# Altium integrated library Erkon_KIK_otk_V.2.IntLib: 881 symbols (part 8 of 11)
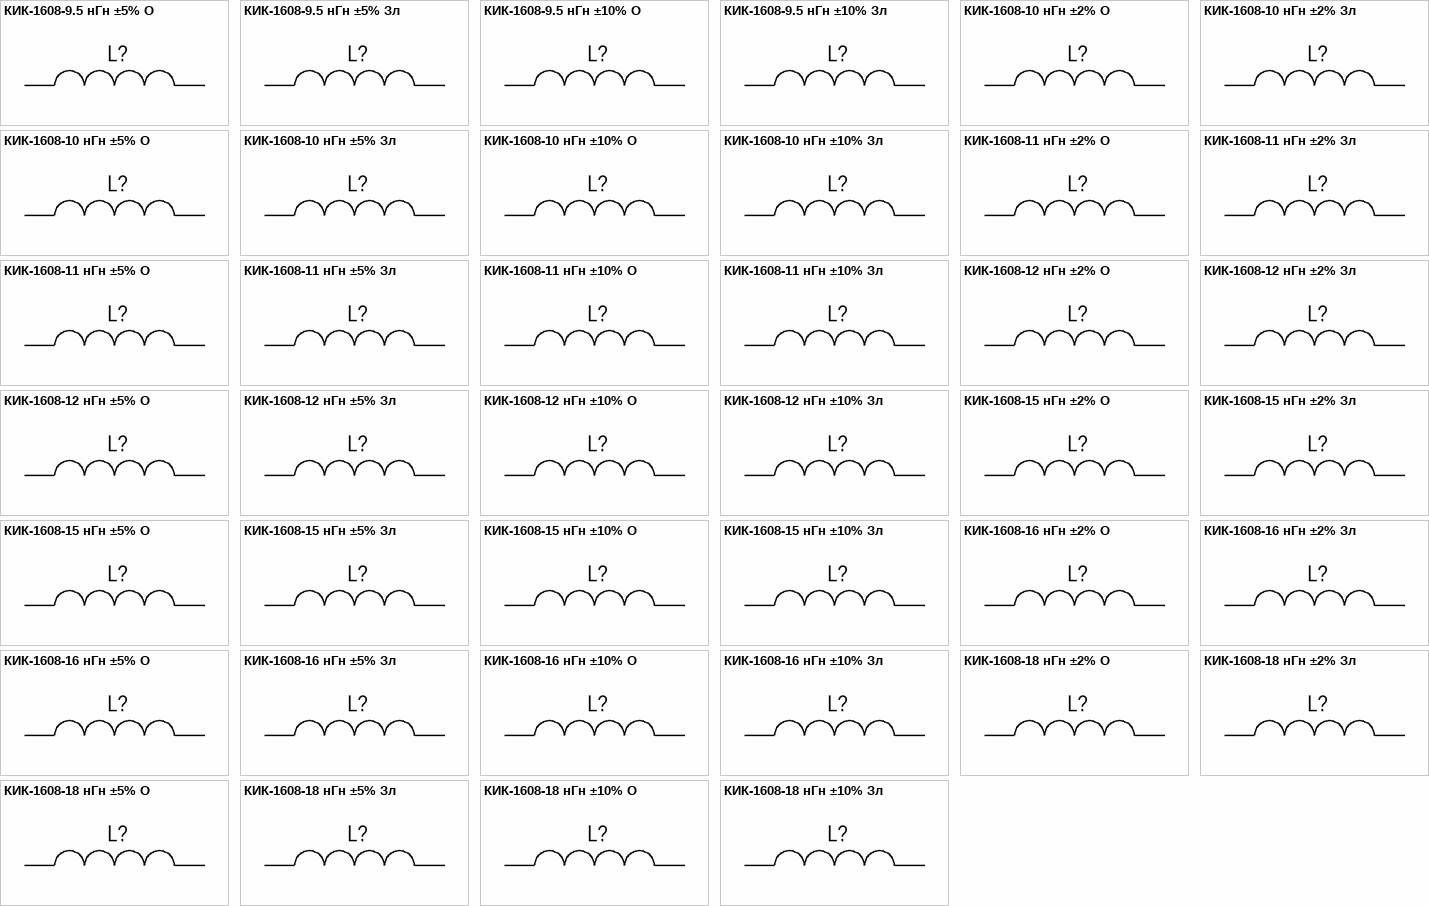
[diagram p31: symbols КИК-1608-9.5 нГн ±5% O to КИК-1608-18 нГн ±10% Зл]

## КИК-1608-15 нГн ±2% Зл
designator L?, comment 15 нГн ±2%  (value not drawn)
Катушка индуктивности с керамическим сердечником и золотым покрытием контактных площадок; Номиналиная индуктивность: 15 нГн; Добротность, не менее: 30; Резонансная частота, не менее: 4.00 ГГц; Сопротивление обмотки постоянноми току, не более: 0.170 Ом; Допустимый ток обмотки: 700 мА; Диапазон рабочих температур: от -60 до +125 ℃; Упаковка: Катушка и лента; Типоразмер: 1608 (0603); Технология монтажа: SMT; Изготовитель: АО "НПО "ЭРКОН"
footprint КИК-1608_Зл (Катушка индуктивности с керамическим сердечником  типоразмер 1005(0402))
pins: 1, 2

## КИК-1608-15 нГн ±5% O
designator L?, comment 15 нГн ±5%  (value not drawn)
Катушка индуктивности с керамическим сердечником и  финишным покрытием контактных площадок оловом; Номиналиная индуктивность: 12 нГн; Добротность, не менее: 30; Резонансная частота, не менее: 4.00 ГГц; Сопротивление обмотки постоянноми току, не более: 0.170 Ом; Допустимый ток обмотки: 700 мА; Диапазон рабочих температур: от -60 до +125 ℃; Упаковка: Катушка и лента; Типоразмер: 1608 (0603); Технология монтажа: SMT; Изготовитель: АО "НПО "ЭРКОН"
footprint КИК-1608_О (Катушка индуктивности с керамическим сердечником  типоразмер 1005(0402))
pins: 1, 2

## КИК-1608-15 нГн ±5% Зл
designator L?, comment 15 нГн ±5%  (value not drawn)
Катушка индуктивности с керамическим сердечником и золотым покрытием контактных площадок; Номиналиная индуктивность: 15 нГн; Добротность, не менее: 30; Резонансная частота, не менее: 4.00 ГГц; Сопротивление обмотки постоянноми току, не более: 0.170 Ом; Допустимый ток обмотки: 700 мА; Диапазон рабочих температур: от -60 до +125 ℃; Упаковка: Катушка и лента; Типоразмер: 1608 (0603); Технология монтажа: SMT; Изготовитель: АО "НПО "ЭРКОН"
footprint КИК-1608_Зл (Катушка индуктивности с керамическим сердечником  типоразмер 1005(0402))
pins: 1, 2

## КИК-1608-15 нГн ±10% O
designator L?, comment 15 нГн ±10%  (value not drawn)
Катушка индуктивности с керамическим сердечником и  финишным покрытием контактных площадок оловом; Номиналиная индуктивность: 15 нГн; Добротность, не менее: 30; Резонансная частота, не менее: 4.00 ГГц; Сопротивление обмотки постоянноми току, не более: 0.170 Ом; Допустимый ток обмотки: 700 мА; Диапазон рабочих температур: от -60 до +125 ℃; Упаковка: Катушка и лента; Типоразмер: 1608 (0603); Технология монтажа: SMT; Изготовитель: АО "НПО "ЭРКОН"
footprint КИК-1608_О (Катушка индуктивности с керамическим сердечником  типоразмер 1005(0402))
pins: 1, 2

## КИК-1608-15 нГн ±10% Зл
designator L?, comment 15 нГн ±10%  (value not drawn)
Катушка индуктивности с керамическим сердечником и золотым покрытием контактных площадок; Номиналиная индуктивность: 15 нГн; Добротность, не менее: 30; Резонансная частота, не менее: 4.00 ГГц; Сопротивление обмотки постоянноми току, не более: 0.170 Ом; Допустимый ток обмотки: 700 мА; Диапазон рабочих температур: от -60 до +125 ℃; Упаковка: Катушка и лента; Типоразмер: 1608 (0603); Технология монтажа: SMT; Изготовитель: АО "НПО "ЭРКОН"
footprint КИК-1608_Зл (Катушка индуктивности с керамическим сердечником  типоразмер 1005(0402))
pins: 1, 2

## КИК-1608-16 нГн ±2% O
designator L?, comment 16 нГн ±2%  (value not drawn)
Катушка индуктивности с керамическим сердечником и  финишным покрытием контактных площадок оловом; Номиналиная индуктивность: 16 нГн; Добротность, не менее: 30; Резонансная частота, не менее: 3.30 ГГц; Сопротивление обмотки постоянноми току, не более: 0.170 Ом; Допустимый ток обмотки: 700 мА; Диапазон рабочих температур: от -60 до +125 ℃; Упаковка: Катушка и лента; Типоразмер: 1608 (0603); Технология монтажа: SMT; Изготовитель: АО "НПО "ЭРКОН"
footprint КИК-1608_О (Катушка индуктивности с керамическим сердечником  типоразмер 1005(0402))
pins: 1, 2

## КИК-1608-16 нГн ±2% Зл
designator L?, comment 16 нГн ±2%  (value not drawn)
Катушка индуктивности с керамическим сердечником и золотым покрытием контактных площадок; Номиналиная индуктивность: 16 нГн; Добротность, не менее: 30; Резонансная частота, не менее: 3.30 ГГц; Сопротивление обмотки постоянноми току, не более: 0.170 Ом; Допустимый ток обмотки: 700 мА; Диапазон рабочих температур: от -60 до +125 ℃; Упаковка: Катушка и лента; Типоразмер: 1608 (0603); Технология монтажа: SMT; Изготовитель: АО "НПО "ЭРКОН"
footprint КИК-1608_Зл (Катушка индуктивности с керамическим сердечником  типоразмер 1005(0402))
pins: 1, 2

## КИК-1608-16 нГн ±5% O
designator L?, comment 16 нГн ±5%  (value not drawn)
Катушка индуктивности с керамическим сердечником и  финишным покрытием контактных площадок оловом; Номиналиная индуктивность: 16 нГн; Добротность, не менее: 30; Резонансная частота, не менее: 3.30 ГГц; Сопротивление обмотки постоянноми току, не более: 0.170 Ом; Допустимый ток обмотки: 700 мА; Диапазон рабочих температур: от -60 до +125 ℃; Упаковка: Катушка и лента; Типоразмер: 1608 (0603); Технология монтажа: SMT; Изготовитель: АО "НПО "ЭРКОН"
footprint КИК-1608_О (Катушка индуктивности с керамическим сердечником  типоразмер 1005(0402))
pins: 1, 2

## КИК-1608-16 нГн ±5% Зл
designator L?, comment 16 нГн ±5%  (value not drawn)
Катушка индуктивности с керамическим сердечником и золотым покрытием контактных площадок; Номиналиная индуктивность: 16 нГн; Добротность, не менее: 30; Резонансная частота, не менее: 3.30 ГГц; Сопротивление обмотки постоянноми току, не более: 0.170 Ом; Допустимый ток обмотки: 700 мА; Диапазон рабочих температур: от -60 до +125 ℃; Упаковка: Катушка и лента; Типоразмер: 1608 (0603); Технология монтажа: SMT; Изготовитель: АО "НПО "ЭРКОН"
footprint КИК-1608_Зл (Катушка индуктивности с керамическим сердечником  типоразмер 1005(0402))
pins: 1, 2

## КИК-1608-16 нГн ±10% O
designator L?, comment 16 нГн ±10%  (value not drawn)
Катушка индуктивности с керамическим сердечником и  финишным покрытием контактных площадок оловом; Номиналиная индуктивность: 16 нГн; Добротность, не менее: 30; Резонансная частота, не менее: 3.30 ГГц; Сопротивление обмотки постоянноми току, не более: 0.170 Ом; Допустимый ток обмотки: 700 мА; Диапазон рабочих температур: от -60 до +125 ℃; Упаковка: Катушка и лента; Типоразмер: 1608 (0603); Технология монтажа: SMT; Изготовитель: АО "НПО "ЭРКОН"
footprint КИК-1608_О (Катушка индуктивности с керамическим сердечником  типоразмер 1005(0402))
pins: 1, 2

## КИК-1608-16 нГн ±10% Зл
designator L?, comment 16 нГн ±10%  (value not drawn)
Катушка индуктивности с керамическим сердечником и золотым покрытием контактных площадок; Номиналиная индуктивность: 16 нГн; Добротность, не менее: 30; Резонансная частота, не менее: 3.30 ГГц; Сопротивление обмотки постоянноми току, не более: 0.170 Ом; Допустимый ток обмотки: 700 мА; Диапазон рабочих температур: от -60 до +125 ℃; Упаковка: Катушка и лента; Типоразмер: 1608 (0603); Технология монтажа: SMT; Изготовитель: АО "НПО "ЭРКОН"
footprint КИК-1608_Зл (Катушка индуктивности с керамическим сердечником  типоразмер 1005(0402))
pins: 1, 2

## КИК-1608-18 нГн ±2% O
designator L?, comment 18 нГн ±2%  (value not drawn)
Катушка индуктивности с керамическим сердечником и  финишным покрытием контактных площадок оловом; Номиналиная индуктивность: 18 нГн; Добротность, не менее: 30; Резонансная частота, не менее: 3.10 ГГц; Сопротивление обмотки постоянноми току, не более: 0.170 Ом; Допустимый ток обмотки: 700 мА; Диапазон рабочих температур: от -60 до +125 ℃; Упаковка: Катушка и лента; Типоразмер: 1608 (0603); Технология монтажа: SMT; Изготовитель: АО "НПО "ЭРКОН"
footprint КИК-1608_О (Катушка индуктивности с керамическим сердечником  типоразмер 1005(0402))
pins: 1, 2

## КИК-1608-18 нГн ±2% Зл
designator L?, comment 18 нГн ±2%  (value not drawn)
Катушка индуктивности с керамическим сердечником и золотым покрытием контактных площадок; Номиналиная индуктивность: 18 нГн; Добротность, не менее: 30; Резонансная частота, не менее: 3.10 ГГц; Сопротивление обмотки постоянноми току, не более: 0.170 Ом; Допустимый ток обмотки: 700 мА; Диапазон рабочих температур: от -60 до +125 ℃; Упаковка: Катушка и лента; Типоразмер: 1608 (0603); Технология монтажа: SMT; Изготовитель: АО "НПО "ЭРКОН"
footprint КИК-1608_Зл (Катушка индуктивности с керамическим сердечником  типоразмер 1005(0402))
pins: 1, 2

## КИК-1608-18 нГн ±5% O
designator L?, comment 18 нГн ±5%  (value not drawn)
Катушка индуктивности с керамическим сердечником и  финишным покрытием контактных площадок оловом; Номиналиная индуктивность: 18 нГн; Добротность, не менее: 30; Резонансная частота, не менее: 3.10 ГГц; Сопротивление обмотки постоянноми току, не более: 0.170 Ом; Допустимый ток обмотки: 700 мА; Диапазон рабочих температур: от -60 до +125 ℃; Упаковка: Катушка и лента; Типоразмер: 1608 (0603); Технология монтажа: SMT; Изготовитель: АО "НПО "ЭРКОН"
footprint КИК-1608_О (Катушка индуктивности с керамическим сердечником  типоразмер 1005(0402))
pins: 1, 2

## КИК-1608-18 нГн ±5% Зл
designator L?, comment 18 нГн ±5%  (value not drawn)
Катушка индуктивности с керамическим сердечником и золотым покрытием контактных площадок; Номиналиная индуктивность: 18 нГн; Добротность, не менее: 30; Резонансная частота, не менее: 3.10 ГГц; Сопротивление обмотки постоянноми току, не более: 0.170 Ом; Допустимый ток обмотки: 700 мА; Диапазон рабочих температур: от -60 до +125 ℃; Упаковка: Катушка и лента; Типоразмер: 1608 (0603); Технология монтажа: SMT; Изготовитель: АО "НПО "ЭРКОН"
footprint КИК-1608_Зл (Катушка индуктивности с керамическим сердечником  типоразмер 1005(0402))
pins: 1, 2

## КИК-1608-18 нГн ±10% O
designator L?, comment 18 нГн ±10%  (value not drawn)
Катушка индуктивности с керамическим сердечником и  финишным покрытием контактных площадок оловом; Номиналиная индуктивность: 18 нГн; Добротность, не менее: 30; Резонансная частота, не менее: 3.10 ГГц; Сопротивление обмотки постоянноми току, не более: 0.170 Ом; Допустимый ток обмотки: 700 мА; Диапазон рабочих температур: от -60 до +125 ℃; Упаковка: Катушка и лента; Типоразмер: 1608 (0603); Технология монтажа: SMT; Изготовитель: АО "НПО "ЭРКОН"
footprint КИК-1608_О (Катушка индуктивности с керамическим сердечником  типоразмер 1005(0402))
pins: 1, 2

## КИК-1608-18 нГн ±10% Зл
designator L?, comment 18 нГн ±10%  (value not drawn)
Катушка индуктивности с керамическим сердечником и золотым покрытием контактных площадок; Номиналиная индуктивность: 18 нГн; Добротность, не менее: 30; Резонансная частота, не менее: 3.10 ГГц; Сопротивление обмотки постоянноми току, не более: 0.170 Ом; Допустимый ток обмотки: 700 мА; Диапазон рабочих температур: от -60 до +125 ℃; Упаковка: Катушка и лента; Типоразмер: 1608 (0603); Технология монтажа: SMT; Изготовитель: АО "НПО "ЭРКОН"
footprint КИК-1608_Зл (Катушка индуктивности с керамическим сердечником  типоразмер 1005(0402))
pins: 1, 2

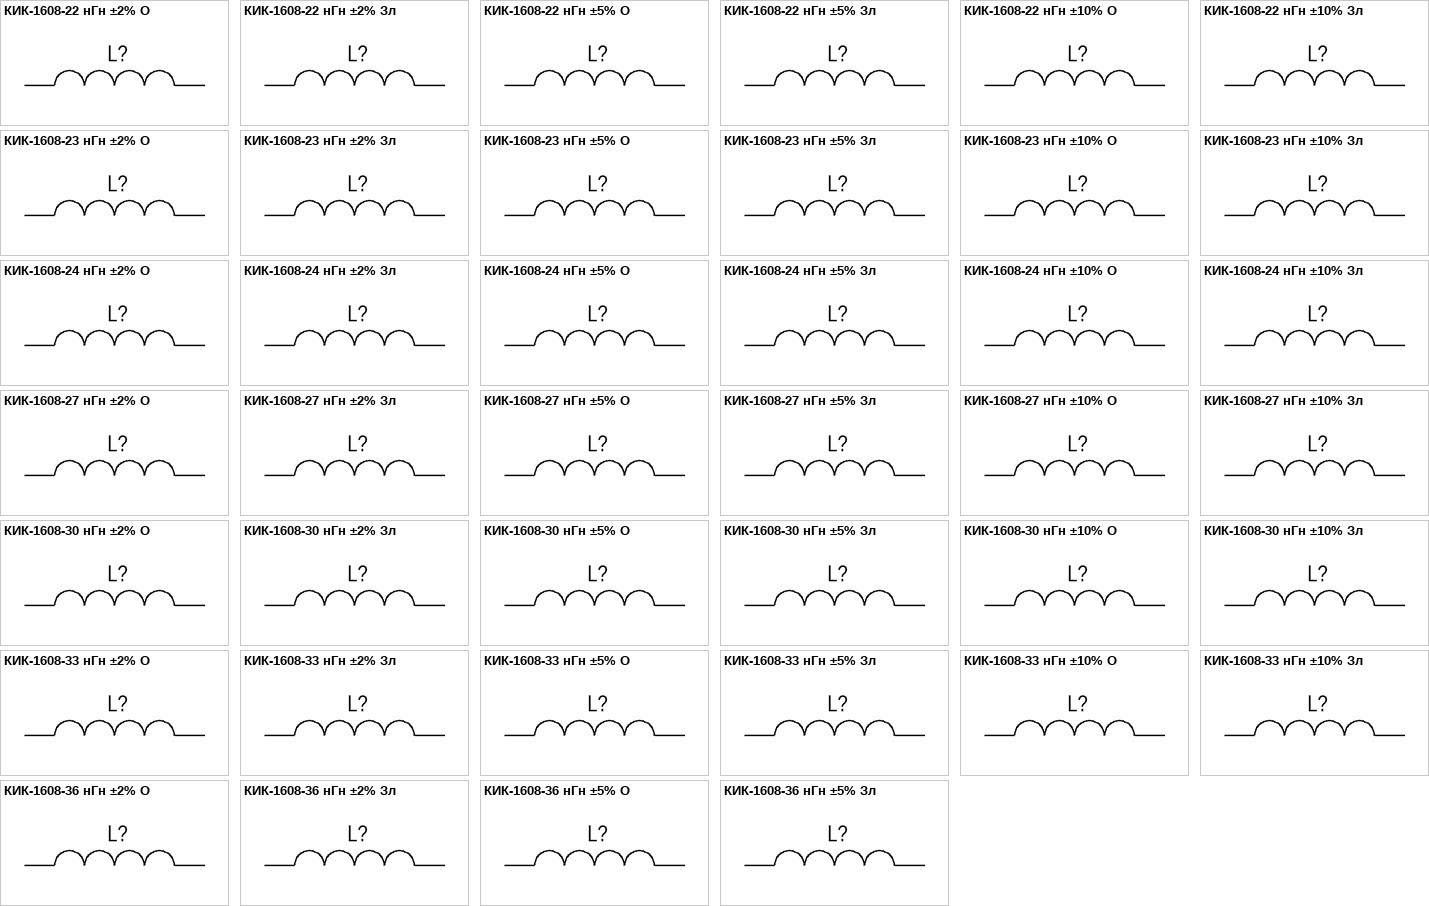
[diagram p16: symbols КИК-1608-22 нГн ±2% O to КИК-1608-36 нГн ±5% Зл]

## КИК-1608-22 нГн ±2% O
designator L?, comment 22 нГн ±2%  (value not drawn)
Катушка индуктивности с керамическим сердечником и  финишным покрытием контактных площадок оловом; Номиналиная индуктивность: 22 нГн; Добротность, не менее: 35; Резонансная частота, не менее: 3.00 ГГц; Сопротивление обмотки постоянноми току, не более: 0.190 Ом; Допустимый ток обмотки: 700 мА; Диапазон рабочих температур: от -60 до +125 ℃; Упаковка: Катушка и лента; Типоразмер: 1608 (0603); Технология монтажа: SMT; Изготовитель: АО "НПО "ЭРКОН"
footprint КИК-1608_О (Катушка индуктивности с керамическим сердечником  типоразмер 1005(0402))
pins: 1, 2

## КИК-1608-22 нГн ±2% Зл
designator L?, comment 22 нГн ±2%  (value not drawn)
Катушка индуктивности с керамическим сердечником и золотым покрытием контактных площадок; Номиналиная индуктивность: 22 нГн; Добротность, не менее: 35; Резонансная частота, не менее: 3.00 ГГц; Сопротивление обмотки постоянноми току, не более: 0.190 Ом; Допустимый ток обмотки: 700 мА; Диапазон рабочих температур: от -60 до +125 ℃; Упаковка: Катушка и лента; Типоразмер: 1608 (0603); Технология монтажа: SMT; Изготовитель: АО "НПО "ЭРКОН"
footprint КИК-1608_Зл (Катушка индуктивности с керамическим сердечником  типоразмер 1005(0402))
pins: 1, 2

## КИК-1608-22 нГн ±5% O
designator L?, comment 22 нГн ±5%  (value not drawn)
Катушка индуктивности с керамическим сердечником и  финишным покрытием контактных площадок оловом; Номиналиная индуктивность: 22 нГн; Добротность, не менее: 35; Резонансная частота, не менее: 3.00 ГГц; Сопротивление обмотки постоянноми току, не более: 0.190 Ом; Допустимый ток обмотки: 700 мА; Диапазон рабочих температур: от -60 до +125 ℃; Упаковка: Катушка и лента; Типоразмер: 1608 (0603); Технология монтажа: SMT; Изготовитель: АО "НПО "ЭРКОН"
footprint КИК-1608_О (Катушка индуктивности с керамическим сердечником  типоразмер 1005(0402))
pins: 1, 2

## КИК-1608-22 нГн ±5% Зл
designator L?, comment 22 нГн ±5%  (value not drawn)
Катушка индуктивности с керамическим сердечником и золотым покрытием контактных площадок; Номиналиная индуктивность: 22 нГн; Добротность, не менее: 35; Резонансная частота, не менее: 3.00 ГГц; Сопротивление обмотки постоянноми току, не более: 0.190 Ом; Допустимый ток обмотки: 700 мА; Диапазон рабочих температур: от -60 до +125 ℃; Упаковка: Катушка и лента; Типоразмер: 1608 (0603); Технология монтажа: SMT; Изготовитель: АО "НПО "ЭРКОН"
footprint КИК-1608_Зл (Катушка индуктивности с керамическим сердечником  типоразмер 1005(0402))
pins: 1, 2

## КИК-1608-22 нГн ±10% O
designator L?, comment 22 нГн ±10%  (value not drawn)
Катушка индуктивности с керамическим сердечником и  финишным покрытием контактных площадок оловом; Номиналиная индуктивность: 22 нГн; Добротность, не менее: 35; Резонансная частота, не менее: 3.00 ГГц; Сопротивление обмотки постоянноми току, не более: 0.190 Ом; Допустимый ток обмотки: 700 мА; Диапазон рабочих температур: от -60 до +125 ℃; Упаковка: Катушка и лента; Типоразмер: 1608 (0603); Технология монтажа: SMT; Изготовитель: АО "НПО "ЭРКОН"
footprint КИК-1608_О (Катушка индуктивности с керамическим сердечником  типоразмер 1005(0402))
pins: 1, 2

## КИК-1608-22 нГн ±10% Зл
designator L?, comment 22 нГн ±10%  (value not drawn)
Катушка индуктивности с керамическим сердечником и золотым покрытием контактных площадок; Номиналиная индуктивность: 22 нГн; Добротность, не менее: 35; Резонансная частота, не менее: 3.00 ГГц; Сопротивление обмотки постоянноми току, не более: 0.190 Ом; Допустимый ток обмотки: 700 мА; Диапазон рабочих температур: от -60 до +125 ℃; Упаковка: Катушка и лента; Типоразмер: 1608 (0603); Технология монтажа: SMT; Изготовитель: АО "НПО "ЭРКОН"
footprint КИК-1608_Зл (Катушка индуктивности с керамическим сердечником  типоразмер 1005(0402))
pins: 1, 2

## КИК-1608-23 нГн ±2% O
designator L?, comment 23 нГн ±2%  (value not drawn)
Катушка индуктивности с керамическим сердечником и  финишным покрытием контактных площадок оловом; Номиналиная индуктивность: 23 нГн; Добротность, не менее: 35; Резонансная частота, не менее: 2.85 ГГц; Сопротивление обмотки постоянноми току, не более: 0.190 Ом; Допустимый ток обмотки: 700 мА; Диапазон рабочих температур: от -60 до +125 ℃; Упаковка: Катушка и лента; Типоразмер: 1608 (0603); Технология монтажа: SMT; Изготовитель: АО "НПО "ЭРКОН"
footprint КИК-1608_О (Катушка индуктивности с керамическим сердечником  типоразмер 1005(0402))
pins: 1, 2

## КИК-1608-23 нГн ±2% Зл
designator L?, comment 23 нГн ±2%  (value not drawn)
Катушка индуктивности с керамическим сердечником и золотым покрытием контактных площадок; Номиналиная индуктивность: 23 нГн; Добротность, не менее: 35; Резонансная частота, не менее: 2.85 ГГц; Сопротивление обмотки постоянноми току, не более: 0.190 Ом; Допустимый ток обмотки: 700 мА; Диапазон рабочих температур: от -60 до +125 ℃; Упаковка: Катушка и лента; Типоразмер: 1608 (0603); Технология монтажа: SMT; Изготовитель: АО "НПО "ЭРКОН"
footprint КИК-1608_Зл (Катушка индуктивности с керамическим сердечником  типоразмер 1005(0402))
pins: 1, 2

## КИК-1608-23 нГн ±5% O
designator L?, comment 23 нГн ±5%  (value not drawn)
Катушка индуктивности с керамическим сердечником и  финишным покрытием контактных площадок оловом; Номиналиная индуктивность: 23 нГн; Добротность, не менее: 35; Резонансная частота, не менее: 2.85 ГГц; Сопротивление обмотки постоянноми току, не более: 0.190 Ом; Допустимый ток обмотки: 700 мА; Диапазон рабочих температур: от -60 до +125 ℃; Упаковка: Катушка и лента; Типоразмер: 1608 (0603); Технология монтажа: SMT; Изготовитель: АО "НПО "ЭРКОН"
footprint КИК-1608_О (Катушка индуктивности с керамическим сердечником  типоразмер 1005(0402))
pins: 1, 2

## КИК-1608-23 нГн ±5% Зл
designator L?, comment 23 нГн ±5%  (value not drawn)
Катушка индуктивности с керамическим сердечником и золотым покрытием контактных площадок; Номиналиная индуктивность: 23 нГн; Добротность, не менее: 35; Резонансная частота, не менее: 2.85 ГГц; Сопротивление обмотки постоянноми току, не более: 0.190 Ом; Допустимый ток обмотки: 700 мА; Диапазон рабочих температур: от -60 до +125 ℃; Упаковка: Катушка и лента; Типоразмер: 1608 (0603); Технология монтажа: SMT; Изготовитель: АО "НПО "ЭРКОН"
footprint КИК-1608_Зл (Катушка индуктивности с керамическим сердечником  типоразмер 1005(0402))
pins: 1, 2

## КИК-1608-23 нГн ±10% O
designator L?, comment 23 нГн ±10%  (value not drawn)
Катушка индуктивности с керамическим сердечником и  финишным покрытием контактных площадок оловом; Номиналиная индуктивность: 23 нГн; Добротность, не менее: 35; Резонансная частота, не менее: 2.85 ГГц; Сопротивление обмотки постоянноми току, не более: 0.190 Ом; Допустимый ток обмотки: 700 мА; Диапазон рабочих температур: от -60 до +125 ℃; Упаковка: Катушка и лента; Типоразмер: 1608 (0603); Технология монтажа: SMT; Изготовитель: АО "НПО "ЭРКОН"
footprint КИК-1608_О (Катушка индуктивности с керамическим сердечником  типоразмер 1005(0402))
pins: 1, 2

## КИК-1608-23 нГн ±10% Зл
designator L?, comment 23 нГн ±10%  (value not drawn)
Катушка индуктивности с керамическим сердечником и золотым покрытием контактных площадок; Номиналиная индуктивность: 23 нГн; Добротность, не менее: 35; Резонансная частота, не менее: 2.85 ГГц; Сопротивление обмотки постоянноми току, не более: 0.190 Ом; Допустимый ток обмотки: 700 мА; Диапазон рабочих температур: от -60 до +125 ℃; Упаковка: Катушка и лента; Типоразмер: 1608 (0603); Технология монтажа: SMT; Изготовитель: АО "НПО "ЭРКОН"
footprint КИК-1608_Зл (Катушка индуктивности с керамическим сердечником  типоразмер 1005(0402))
pins: 1, 2

## КИК-1608-24 нГн ±2% O
designator L?, comment 24 нГн ±2%  (value not drawn)
Катушка индуктивности с керамическим сердечником и  финишным покрытием контактных площадок оловом; Номиналиная индуктивность: 24 нГн; Добротность, не менее: 35; Резонансная частота, не менее: 2.65 ГГц; Сопротивление обмотки постоянноми току, не более: 0.190 Ом; Допустимый ток обмотки: 700 мА; Диапазон рабочих температур: от -60 до +125 ℃; Упаковка: Катушка и лента; Типоразмер: 1608 (0603); Технология монтажа: SMT; Изготовитель: АО "НПО "ЭРКОН"
footprint КИК-1608_О (Катушка индуктивности с керамическим сердечником  типоразмер 1005(0402))
pins: 1, 2

## КИК-1608-24 нГн ±2% Зл
designator L?, comment 24 нГн ±2%  (value not drawn)
Катушка индуктивности с керамическим сердечником и золотым покрытием контактных площадок; Номиналиная индуктивность: 24 нГн; Добротность, не менее: 35; Резонансная частота, не менее: 2.65 ГГц; Сопротивление обмотки постоянноми току, не более: 0.190 Ом; Допустимый ток обмотки: 700 мА; Диапазон рабочих температур: от -60 до +125 ℃; Упаковка: Катушка и лента; Типоразмер: 1608 (0603); Технология монтажа: SMT; Изготовитель: АО "НПО "ЭРКОН"
footprint КИК-1608_Зл (Катушка индуктивности с керамическим сердечником  типоразмер 1005(0402))
pins: 1, 2

## КИК-1608-24 нГн ±5% O
designator L?, comment 24 нГн ±5%  (value not drawn)
Катушка индуктивности с керамическим сердечником и  финишным покрытием контактных площадок оловом; Номиналиная индуктивность: 24 нГн; Добротность, не менее: 35; Резонансная частота, не менее: 2.65 ГГц; Сопротивление обмотки постоянноми току, не более: 0.190 Ом; Допустимый ток обмотки: 700 мА; Диапазон рабочих температур: от -60 до +125 ℃; Упаковка: Катушка и лента; Типоразмер: 1608 (0603); Технология монтажа: SMT; Изготовитель: АО "НПО "ЭРКОН"
footprint КИК-1608_О (Катушка индуктивности с керамическим сердечником  типоразмер 1005(0402))
pins: 1, 2

## КИК-1608-24 нГн ±5% Зл
designator L?, comment 24 нГн ±5%  (value not drawn)
Катушка индуктивности с керамическим сердечником и золотым покрытием контактных площадок; Номиналиная индуктивность: 24 нГн; Добротность, не менее: 35; Резонансная частота, не менее: 2.65 ГГц; Сопротивление обмотки постоянноми току, не более: 0.190 Ом; Допустимый ток обмотки: 700 мА; Диапазон рабочих температур: от -60 до +125 ℃; Упаковка: Катушка и лента; Типоразмер: 1608 (0603); Технология монтажа: SMT; Изготовитель: АО "НПО "ЭРКОН"
footprint КИК-1608_Зл (Катушка индуктивности с керамическим сердечником  типоразмер 1005(0402))
pins: 1, 2

## КИК-1608-24 нГн ±10% O
designator L?, comment 24 нГн ±10%  (value not drawn)
Катушка индуктивности с керамическим сердечником и  финишным покрытием контактных площадок оловом; Номиналиная индуктивность: 24 нГн; Добротность, не менее: 35; Резонансная частота, не менее: 2.65 ГГц; Сопротивление обмотки постоянноми току, не более: 0.190 Ом; Допустимый ток обмотки: 700 мА; Диапазон рабочих температур: от -60 до +125 ℃; Упаковка: Катушка и лента; Типоразмер: 1608 (0603); Технология монтажа: SMT; Изготовитель: АО "НПО "ЭРКОН"
footprint КИК-1608_О (Катушка индуктивности с керамическим сердечником  типоразмер 1005(0402))
pins: 1, 2

## КИК-1608-24 нГн ±10% Зл
designator L?, comment 24 нГн ±10%  (value not drawn)
Катушка индуктивности с керамическим сердечником и золотым покрытием контактных площадок; Номиналиная индуктивность: 24 нГн; Добротность, не менее: 35; Резонансная частота, не менее: 2.65 ГГц; Сопротивление обмотки постоянноми току, не более: 0.190 Ом; Допустимый ток обмотки: 700 мА; Диапазон рабочих температур: от -60 до +125 ℃; Упаковка: Катушка и лента; Типоразмер: 1608 (0603); Технология монтажа: SMT; Изготовитель: АО "НПО "ЭРКОН"
footprint КИК-1608_Зл (Катушка индуктивности с керамическим сердечником  типоразмер 1005(0402))
pins: 1, 2

## КИК-1608-27 нГн ±2% O
designator L?, comment 27 нГн ±2%  (value not drawn)
Катушка индуктивности с керамическим сердечником и  финишным покрытием контактных площадок оловом; Номиналиная индуктивность: 27 нГн; Добротность, не менее: 35; Резонансная частота, не менее: 2.80 ГГц; Сопротивление обмотки постоянноми току, не более: 0.220 Ом; Допустимый ток обмотки: 600 мА; Диапазон рабочих температур: от -60 до +125 ℃; Упаковка: Катушка и лента; Типоразмер: 1608 (0603); Технология монтажа: SMT; Изготовитель: АО "НПО "ЭРКОН"
footprint КИК-1608_О (Катушка индуктивности с керамическим сердечником  типоразмер 1005(0402))
pins: 1, 2

## КИК-1608-27 нГн ±2% Зл
designator L?, comment 27 нГн ±2%  (value not drawn)
Катушка индуктивности с керамическим сердечником и золотым покрытием контактных площадок; Номиналиная индуктивность: 27нГн; Добротность, не менее: 35; Резонансная частота, не менее: 2.80 ГГц; Сопротивление обмотки постоянноми току, не более: 0.220 Ом; Допустимый ток обмотки: 600 мА; Диапазон рабочих температур: от -60 до +125 ℃; Упаковка: Катушка и лента; Типоразмер: 1608 (0603); Технология монтажа: SMT; Изготовитель: АО "НПО "ЭРКОН"
footprint КИК-1608_Зл (Катушка индуктивности с керамическим сердечником  типоразмер 1005(0402))
pins: 1, 2

## КИК-1608-27 нГн ±5% O
designator L?, comment 27 нГн ±5%  (value not drawn)
Катушка индуктивности с керамическим сердечником и  финишным покрытием контактных площадок оловом; Номиналиная индуктивность: 27 нГн; Добротность, не менее: 35; Резонансная частота, не менее: 2.80 ГГц; Сопротивление обмотки постоянноми току, не более: 0.220 Ом; Допустимый ток обмотки: 600 мА; Диапазон рабочих температур: от -60 до +125 ℃; Упаковка: Катушка и лента; Типоразмер: 1608 (0603); Технология монтажа: SMT; Изготовитель: АО "НПО "ЭРКОН"
footprint КИК-1608_О (Катушка индуктивности с керамическим сердечником  типоразмер 1005(0402))
pins: 1, 2

## КИК-1608-27 нГн ±5% Зл
designator L?, comment 27 нГн ±5%  (value not drawn)
Катушка индуктивности с керамическим сердечником и золотым покрытием контактных площадок; Номиналиная индуктивность: 27 нГн; Добротность, не менее: 35; Резонансная частота, не менее: 2.80 ГГц; Сопротивление обмотки постоянноми току, не более: 0.220 Ом; Допустимый ток обмотки: 600 мА; Диапазон рабочих температур: от -60 до +125 ℃; Упаковка: Катушка и лента; Типоразмер: 1608 (0603); Технология монтажа: SMT; Изготовитель: АО "НПО "ЭРКОН"
footprint КИК-1608_Зл (Катушка индуктивности с керамическим сердечником  типоразмер 1005(0402))
pins: 1, 2

## КИК-1608-27 нГн ±10% O
designator L?, comment 27 нГн ±10%  (value not drawn)
Катушка индуктивности с керамическим сердечником и  финишным покрытием контактных площадок оловом; Номиналиная индуктивность: 27 нГн; Добротность, не менее: 35; Резонансная частота, не менее: 2.80 ГГц; Сопротивление обмотки постоянноми току, не более: 0.220 Ом; Допустимый ток обмотки: 600 мА; Диапазон рабочих температур: от -60 до +125 ℃; Упаковка: Катушка и лента; Типоразмер: 1608 (0603); Технология монтажа: SMT; Изготовитель: АО "НПО "ЭРКОН"
footprint КИК-1608_О (Катушка индуктивности с керамическим сердечником  типоразмер 1005(0402))
pins: 1, 2

## КИК-1608-27 нГн ±10% Зл
designator L?, comment 27 нГн ±10%  (value not drawn)
Катушка индуктивности с керамическим сердечником и золотым покрытием контактных площадок; Номиналиная индуктивность: 27нГн; Добротность, не менее: 35; Резонансная частота, не менее: 2.80 ГГц; Сопротивление обмотки постоянноми току, не более: 0.220 Ом; Допустимый ток обмотки: 600 мА; Диапазон рабочих температур: от -60 до +125 ℃; Упаковка: Катушка и лента; Типоразмер: 1608 (0603); Технология монтажа: SMT; Изготовитель: АО "НПО "ЭРКОН"
footprint КИК-1608_Зл (Катушка индуктивности с керамическим сердечником  типоразмер 1005(0402))
pins: 1, 2

## КИК-1608-30 нГн ±2% O
designator L?, comment 30 нГн ±2%  (value not drawn)
Катушка индуктивности с керамическим сердечником и  финишным покрытием контактных площадок оловом; Номиналиная индуктивность: 30 нГн; Добротность, не менее: 35; Резонансная частота, не менее: 2.25 ГГц; Сопротивление обмотки постоянноми току, не более: 0.220 Ом; Допустимый ток обмотки: 600 мА; Диапазон рабочих температур: от -60 до +125 ℃; Упаковка: Катушка и лента; Типоразмер: 1608 (0603); Технология монтажа: SMT; Изготовитель: АО "НПО "ЭРКОН"
footprint КИК-1608_О (Катушка индуктивности с керамическим сердечником  типоразмер 1005(0402))
pins: 1, 2

## КИК-1608-30 нГн ±2% Зл
designator L?, comment 30 нГн ±2%  (value not drawn)
Катушка индуктивности с керамическим сердечником и золотым покрытием контактных площадок; Номиналиная индуктивность: 30 нГн; Добротность, не менее: 35; Резонансная частота, не менее: 2.25 ГГц; Сопротивление обмотки постоянноми току, не более: 0.220 Ом; Допустимый ток обмотки: 600 мА; Диапазон рабочих температур: от -60 до +125 ℃; Упаковка: Катушка и лента; Типоразмер: 1608 (0603); Технология монтажа: SMT; Изготовитель: АО "НПО "ЭРКОН"
footprint КИК-1608_Зл (Катушка индуктивности с керамическим сердечником  типоразмер 1005(0402))
pins: 1, 2

## КИК-1608-30 нГн ±5% O
designator L?, comment 30 нГн ±5%  (value not drawn)
Катушка индуктивности с керамическим сердечником и  финишным покрытием контактных площадок оловом; Номиналиная индуктивность: 30 нГн; Добротность, не менее: 35; Резонансная частота, не менее: 2.25 ГГц; Сопротивление обмотки постоянноми току, не более: 0.220 Ом; Допустимый ток обмотки: 600 мА; Диапазон рабочих температур: от -60 до +125 ℃; Упаковка: Катушка и лента; Типоразмер: 1608 (0603); Технология монтажа: SMT; Изготовитель: АО "НПО "ЭРКОН"
footprint КИК-1608_О (Катушка индуктивности с керамическим сердечником  типоразмер 1005(0402))
pins: 1, 2

## КИК-1608-30 нГн ±5% Зл
designator L?, comment 30 нГн ±5%  (value not drawn)
Катушка индуктивности с керамическим сердечником и золотым покрытием контактных площадок; Номиналиная индуктивность: 30 нГн; Добротность, не менее: 35; Резонансная частота, не менее: 2.25 ГГц; Сопротивление обмотки постоянноми току, не более: 0.220 Ом; Допустимый ток обмотки: 600 мА; Диапазон рабочих температур: от -60 до +125 ℃; Упаковка: Катушка и лента; Типоразмер: 1608 (0603); Технология монтажа: SMT; Изготовитель: АО "НПО "ЭРКОН"
footprint КИК-1608_Зл (Катушка индуктивности с керамическим сердечником  типоразмер 1005(0402))
pins: 1, 2

## КИК-1608-30 нГн ±10% O
designator L?, comment 30 нГн ±10%  (value not drawn)
Катушка индуктивности с керамическим сердечником и  финишным покрытием контактных площадок оловом; Номиналиная индуктивность: 30 нГн; Добротность, не менее: 35; Резонансная частота, не менее: 2.25 ГГц; Сопротивление обмотки постоянноми току, не более: 0.220 Ом; Допустимый ток обмотки: 600 мА; Диапазон рабочих температур: от -60 до +125 ℃; Упаковка: Катушка и лента; Типоразмер: 1608 (0603); Технология монтажа: SMT; Изготовитель: АО "НПО "ЭРКОН"
footprint КИК-1608_О (Катушка индуктивности с керамическим сердечником  типоразмер 1005(0402))
pins: 1, 2

## КИК-1608-30 нГн ±10% Зл
designator L?, comment 30 нГн ±10%  (value not drawn)
Катушка индуктивности с керамическим сердечником и золотым покрытием контактных площадок; Номиналиная индуктивность: 30 нГн; Добротность, не менее: 35; Резонансная частота, не менее: 2.25 ГГц; Сопротивление обмотки постоянноми току, не более: 0.220 Ом; Допустимый ток обмотки: 600 мА; Диапазон рабочих температур: от -60 до +125 ℃; Упаковка: Катушка и лента; Типоразмер: 1608 (0603); Технология монтажа: SMT; Изготовитель: АО "НПО "ЭРКОН"
footprint КИК-1608_Зл (Катушка индуктивности с керамическим сердечником  типоразмер 1005(0402))
pins: 1, 2

## КИК-1608-33 нГн ±2% O
designator L?, comment 33 нГн ±2%  (value not drawn)
Катушка индуктивности с керамическим сердечником и  финишным покрытием контактных площадок оловом; Номиналиная индуктивность: 33 нГн; Добротность, не менее: 35; Резонансная частота, не менее: 2.30 ГГц; Сопротивление обмотки постоянноми току, не более: 0.220 Ом; Допустимый ток обмотки: 600 мА; Диапазон рабочих температур: от -60 до +125 ℃; Упаковка: Катушка и лента; Типоразмер: 1608 (0603); Технология монтажа: SMT; Изготовитель: АО "НПО "ЭРКОН"
footprint КИК-1608_О (Катушка индуктивности с керамическим сердечником  типоразмер 1005(0402))
pins: 1, 2

## КИК-1608-33 нГн ±2% Зл
designator L?, comment 33 нГн ±2%  (value not drawn)
Катушка индуктивности с керамическим сердечником и золотым покрытием контактных площадок; Номиналиная индуктивность: 33 нГн; Добротность, не менее: 35; Резонансная частота, не менее: 2.30 ГГц; Сопротивление обмотки постоянноми току, не более: 0.220 Ом; Допустимый ток обмотки: 600 мА; Диапазон рабочих температур: от -60 до +125 ℃; Упаковка: Катушка и лента; Типоразмер: 1608 (0603); Технология монтажа: SMT; Изготовитель: АО "НПО "ЭРКОН"
footprint КИК-1608_Зл (Катушка индуктивности с керамическим сердечником  типоразмер 1005(0402))
pins: 1, 2

## КИК-1608-33 нГн ±5% O
designator L?, comment 33 нГн ±5%  (value not drawn)
Катушка индуктивности с керамическим сердечником и  финишным покрытием контактных площадок оловом; Номиналиная индуктивность: 33 нГн; Добротность, не менее: 35; Резонансная частота, не менее: 2.30 ГГц; Сопротивление обмотки постоянноми току, не более: 0.220 Ом; Допустимый ток обмотки: 600 мА; Диапазон рабочих температур: от -60 до +125 ℃; Упаковка: Катушка и лента; Типоразмер: 1608 (0603); Технология монтажа: SMT; Изготовитель: АО "НПО "ЭРКОН"
footprint КИК-1608_О (Катушка индуктивности с керамическим сердечником  типоразмер 1005(0402))
pins: 1, 2

## КИК-1608-33 нГн ±5% Зл
designator L?, comment 33 нГн ±5%  (value not drawn)
Катушка индуктивности с керамическим сердечником и золотым покрытием контактных площадок; Номиналиная индуктивность: 33 нГн; Добротность, не менее: 35; Резонансная частота, не менее: 2.30 ГГц; Сопротивление обмотки постоянноми току, не более: 0.220 Ом; Допустимый ток обмотки: 600 мА; Диапазон рабочих температур: от -60 до +125 ℃; Упаковка: Катушка и лента; Типоразмер: 1608 (0603); Технология монтажа: SMT; Изготовитель: АО "НПО "ЭРКОН"
footprint КИК-1608_Зл (Катушка индуктивности с керамическим сердечником  типоразмер 1005(0402))
pins: 1, 2

## КИК-1608-33 нГн ±10% O
designator L?, comment 33 нГн ±10%  (value not drawn)
Катушка индуктивности с керамическим сердечником и  финишным покрытием контактных площадок оловом; Номиналиная индуктивность: 33 нГн; Добротность, не менее: 35; Резонансная частота, не менее: 2.30 ГГц; Сопротивление обмотки постоянноми току, не более: 0.220 Ом; Допустимый ток обмотки: 600 мА; Диапазон рабочих температур: от -60 до +125 ℃; Упаковка: Катушка и лента; Типоразмер: 1608 (0603); Технология монтажа: SMT; Изготовитель: АО "НПО "ЭРКОН"
footprint КИК-1608_О (Катушка индуктивности с керамическим сердечником  типоразмер 1005(0402))
pins: 1, 2

## КИК-1608-33 нГн ±10% Зл
designator L?, comment 33 нГн ±10%  (value not drawn)
Катушка индуктивности с керамическим сердечником и золотым покрытием контактных площадок; Номиналиная индуктивность: 33 нГн; Добротность, не менее: 35; Резонансная частота, не менее: 2.30 ГГц; Сопротивление обмотки постоянноми току, не более: 0.220 Ом; Допустимый ток обмотки: 600 мА; Диапазон рабочих температур: от -60 до +125 ℃; Упаковка: Катушка и лента; Типоразмер: 1608 (0603); Технология монтажа: SMT; Изготовитель: АО "НПО "ЭРКОН"
footprint КИК-1608_Зл (Катушка индуктивности с керамическим сердечником  типоразмер 1005(0402))
pins: 1, 2

## КИК-1608-36 нГн ±2% O
designator L?, comment 36 нГн ±2%  (value not drawn)
Катушка индуктивности с керамическим сердечником и  финишным покрытием контактных площадок оловом; Номиналиная индуктивность: 36 нГн; Добротность, не менее: 35; Резонансная частота, не менее: 2.08ГГц; Сопротивление обмотки постоянноми току, не более: 0.250 Ом; Допустимый ток обмотки: 600 мА; Диапазон рабочих температур: от -60 до +125 ℃; Упаковка: Катушка и лента; Типоразмер: 1608 (0603); Технология монтажа: SMT; Изготовитель: АО "НПО "ЭРКОН"
footprint КИК-1608_О (Катушка индуктивности с керамическим сердечником  типоразмер 1005(0402))
pins: 1, 2

## КИК-1608-36 нГн ±2% Зл
designator L?, comment 36 нГн ±2%  (value not drawn)
Катушка индуктивности с керамическим сердечником и золотым покрытием контактных площадок; Номиналиная индуктивность: 36 нГн; Добротность, не менее: 35; Резонансная частота, не менее: 2.08ГГц; Сопротивление обмотки постоянноми току, не более: 0.250 Ом; Допустимый ток обмотки: 600 мА; Диапазон рабочих температур: от -60 до +125 ℃; Упаковка: Катушка и лента; Типоразмер: 1608 (0603); Технология монтажа: SMT; Изготовитель: АО "НПО "ЭРКОН"
footprint КИК-1608_Зл (Катушка индуктивности с керамическим сердечником  типоразмер 1005(0402))
pins: 1, 2

## КИК-1608-36 нГн ±5% O
designator L?, comment 36 нГн ±5%  (value not drawn)
Катушка индуктивности с керамическим сердечником и  финишным покрытием контактных площадок оловом; Номиналиная индуктивность: 36 нГн; Добротность, не менее: 35; Резонансная частота, не менее: 2.08ГГц; Сопротивление обмотки постоянноми току, не более: 0.250 Ом; Допустимый ток обмотки: 600 мА; Диапазон рабочих температур: от -60 до +125 ℃; Упаковка: Катушка и лента; Типоразмер: 1608 (0603); Технология монтажа: SMT; Изготовитель: АО "НПО "ЭРКОН"
footprint КИК-1608_О (Катушка индуктивности с керамическим сердечником  типоразмер 1005(0402))
pins: 1, 2

## КИК-1608-36 нГн ±5% Зл
designator L?, comment 36 нГн ±5%  (value not drawn)
Катушка индуктивности с керамическим сердечником и золотым покрытием контактных площадок; Номиналиная индуктивность: 36 нГн; Добротность, не менее: 35; Резонансная частота, не менее: 2.08ГГц; Сопротивление обмотки постоянноми току, не более: 0.250 Ом; Допустимый ток обмотки: 600 мА; Диапазон рабочих температур: от -60 до +125 ℃; Упаковка: Катушка и лента; Типоразмер: 1608 (0603); Технология монтажа: SMT; Изготовитель: АО "НПО "ЭРКОН"
footprint КИК-1608_Зл (Катушка индуктивности с керамическим сердечником  типоразмер 1005(0402))
pins: 1, 2

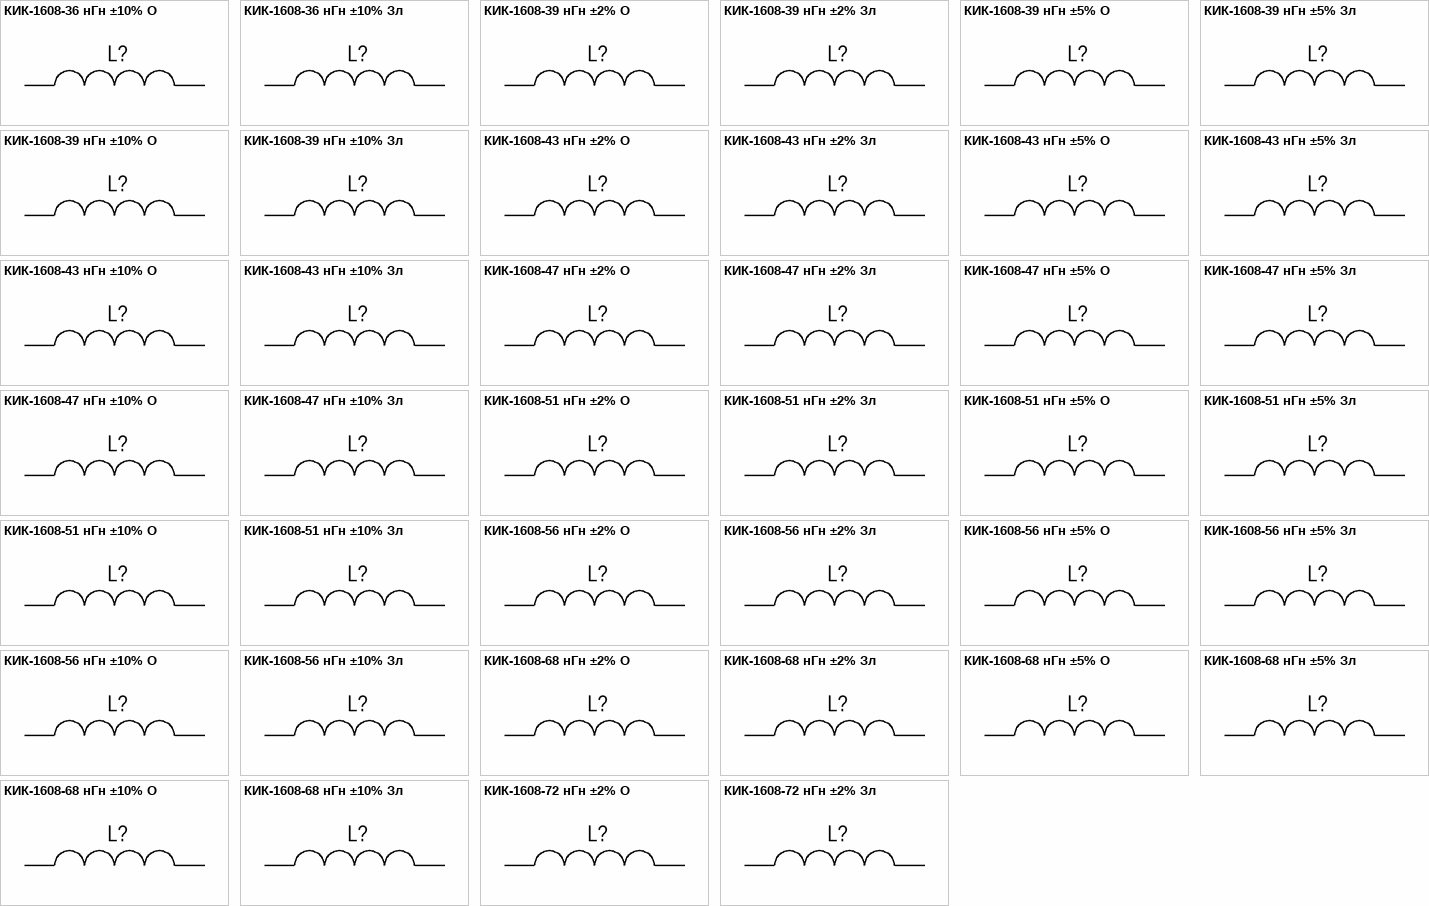
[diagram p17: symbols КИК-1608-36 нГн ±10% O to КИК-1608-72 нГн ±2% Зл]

## КИК-1608-36 нГн ±10% O
designator L?, comment 36 нГн ±10%  (value not drawn)
Катушка индуктивности с керамическим сердечником и  финишным покрытием контактных площадок оловом; Номиналиная индуктивность: 36 нГн; Добротность, не менее: 35; Резонансная частота, не менее: 2.08ГГц; Сопротивление обмотки постоянноми току, не более: 0.250 Ом; Допустимый ток обмотки: 600 мА; Диапазон рабочих температур: от -60 до +125 ℃; Упаковка: Катушка и лента; Типоразмер: 1608 (0603); Технология монтажа: SMT; Изготовитель: АО "НПО "ЭРКОН"
footprint КИК-1608_О (Катушка индуктивности с керамическим сердечником  типоразмер 1005(0402))
pins: 1, 2

## КИК-1608-36 нГн ±10% Зл
designator L?, comment 36 нГн ±10%  (value not drawn)
Катушка индуктивности с керамическим сердечником и золотым покрытием контактных площадок; Номиналиная индуктивность: 36 нГн; Добротность, не менее: 35; Резонансная частота, не менее: 2.08ГГц; Сопротивление обмотки постоянноми току, не более: 0.250 Ом; Допустимый ток обмотки: 600 мА; Диапазон рабочих температур: от -60 до +125 ℃; Упаковка: Катушка и лента; Типоразмер: 1608 (0603); Технология монтажа: SMT; Изготовитель: АО "НПО "ЭРКОН"
footprint КИК-1608_Зл (Катушка индуктивности с керамическим сердечником  типоразмер 1005(0402))
pins: 1, 2

## КИК-1608-39 нГн ±2% O
designator L?, comment 39 нГн ±2%  (value not drawn)
Катушка индуктивности с керамическим сердечником и  финишным покрытием контактных площадок оловом; Номиналиная индуктивность: 39 нГн; Добротность, не менее: 35; Резонансная частота, не менее: 2.20 ГГц; Сопротивление обмотки постоянноми току, не более: 0.250 Ом; Допустимый ток обмотки: 600 мА; Диапазон рабочих температур: от -60 до +125 ℃; Упаковка: Катушка и лента; Типоразмер: 1608 (0603); Технология монтажа: SMT; Изготовитель: АО "НПО "ЭРКОН"
footprint КИК-1608_О (Катушка индуктивности с керамическим сердечником  типоразмер 1005(0402))
pins: 1, 2

## КИК-1608-39 нГн ±2% Зл
designator L?, comment 39 нГн ±2%  (value not drawn)
Катушка индуктивности с керамическим сердечником и золотым покрытием контактных площадок; Номиналиная индуктивность: 39 нГн; Добротность, не менее: 35; Резонансная частота, не менее: 2.20 ГГц; Сопротивление обмотки постоянноми току, не более: 0.250 Ом; Допустимый ток обмотки: 600 мА; Диапазон рабочих температур: от -60 до +125 ℃; Упаковка: Катушка и лента; Типоразмер: 1608 (0603); Технология монтажа: SMT; Изготовитель: АО "НПО "ЭРКОН"
footprint КИК-1608_Зл (Катушка индуктивности с керамическим сердечником  типоразмер 1005(0402))
pins: 1, 2

## КИК-1608-39 нГн ±5% O
designator L?, comment 39 нГн ±5%  (value not drawn)
Катушка индуктивности с керамическим сердечником и  финишным покрытием контактных площадок оловом; Номиналиная индуктивность: 39 нГн; Добротность, не менее: 35; Резонансная частота, не менее: 2.20 ГГц; Сопротивление обмотки постоянноми току, не более: 0.250 Ом; Допустимый ток обмотки: 600 мА; Диапазон рабочих температур: от -60 до +125 ℃; Упаковка: Катушка и лента; Типоразмер: 1608 (0603); Технология монтажа: SMT; Изготовитель: АО "НПО "ЭРКОН"
footprint КИК-1608_О (Катушка индуктивности с керамическим сердечником  типоразмер 1005(0402))
pins: 1, 2

## КИК-1608-39 нГн ±5% Зл
designator L?, comment 39 нГн ±5%  (value not drawn)
Катушка индуктивности с керамическим сердечником и золотым покрытием контактных площадок; Номиналиная индуктивность: 39 нГн; Добротность, не менее: 35; Резонансная частота, не менее: 2.20 ГГц; Сопротивление обмотки постоянноми току, не более: 0.250 Ом; Допустимый ток обмотки: 600 мА; Диапазон рабочих температур: от -60 до +125 ℃; Упаковка: Катушка и лента; Типоразмер: 1608 (0603); Технология монтажа: SMT; Изготовитель: АО "НПО "ЭРКОН"
footprint КИК-1608_Зл (Катушка индуктивности с керамическим сердечником  типоразмер 1005(0402))
pins: 1, 2

## КИК-1608-39 нГн ±10% O
designator L?, comment 39 нГн ±10%  (value not drawn)
Катушка индуктивности с керамическим сердечником и  финишным покрытием контактных площадок оловом; Номиналиная индуктивность: 39 нГн; Добротность, не менее: 35; Резонансная частота, не менее: 2.20 ГГц; Сопротивление обмотки постоянноми току, не более: 0.250 Ом; Допустимый ток обмотки: 600 мА; Диапазон рабочих температур: от -60 до +125 ℃; Упаковка: Катушка и лента; Типоразмер: 1608 (0603); Технология монтажа: SMT; Изготовитель: АО "НПО "ЭРКОН"
footprint КИК-1608_О (Катушка индуктивности с керамическим сердечником  типоразмер 1005(0402))
pins: 1, 2

## КИК-1608-39 нГн ±10% Зл
designator L?, comment 39 нГн ±10%  (value not drawn)
Катушка индуктивности с керамическим сердечником и золотым покрытием контактных площадок; Номиналиная индуктивность: 39 нГн; Добротность, не менее: 35; Резонансная частота, не менее: 2.20 ГГц; Сопротивление обмотки постоянноми току, не более: 0.250 Ом; Допустимый ток обмотки: 600 мА; Диапазон рабочих температур: от -60 до +125 ℃; Упаковка: Катушка и лента; Типоразмер: 1608 (0603); Технология монтажа: SMT; Изготовитель: АО "НПО "ЭРКОН"
footprint КИК-1608_Зл (Катушка индуктивности с керамическим сердечником  типоразмер 1005(0402))
pins: 1, 2

## КИК-1608-43 нГн ±2% O
designator L?, comment 43 нГн ±5%  (value not drawn)
Катушка индуктивности с керамическим сердечником и  финишным покрытием контактных площадок оловом; Номиналиная индуктивность: 43 нГн; Допускаемое отклонение индуктивности: ±2%; Добротность, не менее: 35; Резонансная частота, не менее: 2.00 ГГц; Сопротивление обмотки постоянноми току, не более: 0.280 Ом; Допустимый ток обмотки: 600 мА; Диапазон рабочих температур: от -60 до +125 ℃; Упаковка: Катушка и лента; Типоразмер: 1608 (0603); Технология монтажа: SMT; Изготовитель: АО "НПО "ЭРКОН"
footprint КИК-1608_О (Катушка индуктивности с керамическим сердечником  типоразмер 1005(0402))
pins: 1, 2

## КИК-1608-43 нГн ±2% Зл
designator L?, comment 43 нГн ±2%  (value not drawn)
Катушка индуктивности с керамическим сердечником и золотым покрытием контактных площадок; Номиналиная индуктивность: 43 нГн; Добротность, не менее: 35; Резонансная частота, не менее: 2.00 ГГц; Сопротивление обмотки постоянноми току, не более: 0.280 Ом; Допустимый ток обмотки: 600 мА; Диапазон рабочих температур: от -60 до +125 ℃; Упаковка: Катушка и лента; Типоразмер: 1608 (0603); Технология монтажа: SMT; Изготовитель: АО "НПО "ЭРКОН"
footprint КИК-1608_Зл (Катушка индуктивности с керамическим сердечником  типоразмер 1005(0402))
pins: 1, 2

## КИК-1608-43 нГн ±5% O
designator L?, comment 43 нГн ±5%  (value not drawn)
Катушка индуктивности с керамическим сердечником и  финишным покрытием контактных площадок оловом; Номиналиная индуктивность: 43 нГн; Добротность, не менее: 35; Резонансная частота, не менее: 2.00 ГГц; Сопротивление обмотки постоянноми току, не более: 0.280 Ом; Допустимый ток обмотки: 600 мА; Диапазон рабочих температур: от -60 до +125 ℃; Упаковка: Катушка и лента; Типоразмер: 1608 (0603); Технология монтажа: SMT; Изготовитель: АО "НПО "ЭРКОН"
footprint КИК-1608_О (Катушка индуктивности с керамическим сердечником  типоразмер 1005(0402))
pins: 1, 2

## КИК-1608-43 нГн ±5% Зл
designator L?, comment 43 нГн ±5%  (value not drawn)
Катушка индуктивности с керамическим сердечником и золотым покрытием контактных площадок; Номиналиная индуктивность: 43 нГн; Добротность, не менее: 35; Резонансная частота, не менее: 2.00 ГГц; Сопротивление обмотки постоянноми току, не более: 0.280 Ом; Допустимый ток обмотки: 600 мА; Диапазон рабочих температур: от -60 до +125 ℃; Упаковка: Катушка и лента; Типоразмер: 1608 (0603); Технология монтажа: SMT; Изготовитель: АО "НПО "ЭРКОН"
footprint КИК-1608_Зл (Катушка индуктивности с керамическим сердечником  типоразмер 1005(0402))
pins: 1, 2

## КИК-1608-43 нГн ±10% O
designator L?, comment 43 нГн ±10%  (value not drawn)
Катушка индуктивности с керамическим сердечником и  финишным покрытием контактных площадок оловом; Номиналиная индуктивность: 43 нГн; Добротность, не менее: 35; Резонансная частота, не менее: 2.00 ГГц; Сопротивление обмотки постоянноми току, не более: 0.280 Ом; Допустимый ток обмотки: 600 мА; Диапазон рабочих температур: от -60 до +125 ℃; Упаковка: Катушка и лента; Типоразмер: 1608 (0603); Технология монтажа: SMT; Изготовитель: АО "НПО "ЭРКОН"
footprint КИК-1608_О (Катушка индуктивности с керамическим сердечником  типоразмер 1005(0402))
pins: 1, 2

## КИК-1608-43 нГн ±10% Зл
designator L?, comment 43 нГн ±10%  (value not drawn)
Катушка индуктивности с керамическим сердечником и золотым покрытием контактных площадок; Номиналиная индуктивность: 43 нГн; Добротность, не менее: 35; Резонансная частота, не менее: 2.00 ГГц; Сопротивление обмотки постоянноми току, не более: 0.280 Ом; Допустимый ток обмотки: 600 мА; Диапазон рабочих температур: от -60 до +125 ℃; Упаковка: Катушка и лента; Типоразмер: 1608 (0603); Технология монтажа: SMT; Изготовитель: АО "НПО "ЭРКОН"
footprint КИК-1608_Зл (Катушка индуктивности с керамическим сердечником  типоразмер 1005(0402))
pins: 1, 2

## КИК-1608-47 нГн ±2% O
designator L?, comment 47 нГн ±2%  (value not drawn)
Катушка индуктивности с керамическим сердечником и  финишным покрытием контактных площадок оловом; Номиналиная индуктивность: 47 нГн; Добротность, не менее: 35; Резонансная частота, не менее: 2.00 ГГц; Сопротивление обмотки постоянноми току, не более: 0.280 Ом; Допустимый ток обмотки: 600 мА; Диапазон рабочих температур: от -60 до +125 ℃; Упаковка: Катушка и лента; Типоразмер: 1608 (0603); Технология монтажа: SMT; Изготовитель: АО "НПО "ЭРКОН"
footprint КИК-1608_О (Катушка индуктивности с керамическим сердечником  типоразмер 1005(0402))
pins: 1, 2

## КИК-1608-47 нГн ±2% Зл
designator L?, comment 47 нГн ±2%  (value not drawn)
Катушка индуктивности с керамическим сердечником и золотым покрытием контактных площадок; Номиналиная индуктивность: 47 нГн; Добротность, не менее: 35; Резонансная частота, не менее: 2.00 ГГц; Сопротивление обмотки постоянноми току, не более: 0.280 Ом; Допустимый ток обмотки: 600 мА; Диапазон рабочих температур: от -60 до +125 ℃; Упаковка: Катушка и лента; Типоразмер: 1608 (0603); Технология монтажа: SMT; Изготовитель: АО "НПО "ЭРКОН"
footprint КИК-1608_Зл (Катушка индуктивности с керамическим сердечником  типоразмер 1005(0402))
pins: 1, 2

## КИК-1608-47 нГн ±5% O
designator L?, comment 47 нГн ±5%  (value not drawn)
Катушка индуктивности с керамическим сердечником и  финишным покрытием контактных площадок оловом; Номиналиная индуктивность: 47 нГн; Добротность, не менее: 35; Резонансная частота, не менее: 2.00 ГГц; Сопротивление обмотки постоянноми току, не более: 0.280 Ом; Допустимый ток обмотки: 600 мА; Диапазон рабочих температур: от -60 до +125 ℃; Упаковка: Катушка и лента; Типоразмер: 1608 (0603); Технология монтажа: SMT; Изготовитель: АО "НПО "ЭРКОН"
footprint КИК-1608_О (Катушка индуктивности с керамическим сердечником  типоразмер 1005(0402))
pins: 1, 2

## КИК-1608-47 нГн ±5% Зл
designator L?, comment 47 нГн ±5%  (value not drawn)
Катушка индуктивности с керамическим сердечником и золотым покрытием контактных площадок; Номиналиная индуктивность: 47 нГн; Добротность, не менее: 35; Резонансная частота, не менее: 2.00 ГГц; Сопротивление обмотки постоянноми току, не более: 0.280 Ом; Допустимый ток обмотки: 600 мА; Диапазон рабочих температур: от -60 до +125 ℃; Упаковка: Катушка и лента; Типоразмер: 1608 (0603); Технология монтажа: SMT; Изготовитель: АО "НПО "ЭРКОН"
footprint КИК-1608_Зл (Катушка индуктивности с керамическим сердечником  типоразмер 1005(0402))
pins: 1, 2

## КИК-1608-47 нГн ±10% O
designator L?, comment 47 нГн ±10%  (value not drawn)
Катушка индуктивности с керамическим сердечником и  финишным покрытием контактных площадок оловом; Номиналиная индуктивность: 47 нГн; Добротность, не менее: 35; Резонансная частота, не менее: 2.00 ГГц; Сопротивление обмотки постоянноми току, не более: 0.280 Ом; Допустимый ток обмотки: 600 мА; Диапазон рабочих температур: от -60 до +125 ℃; Упаковка: Катушка и лента; Типоразмер: 1608 (0603); Технология монтажа: SMT; Изготовитель: АО "НПО "ЭРКОН"
footprint КИК-1608_О (Катушка индуктивности с керамическим сердечником  типоразмер 1005(0402))
pins: 1, 2

## КИК-1608-47 нГн ±10% Зл
designator L?, comment 47 нГн ±10%  (value not drawn)
Катушка индуктивности с керамическим сердечником и золотым покрытием контактных площадок; Номиналиная индуктивность: 47 нГн; Добротность, не менее: 35; Резонансная частота, не менее: 2.00 ГГц; Сопротивление обмотки постоянноми току, не более: 0.280 Ом; Допустимый ток обмотки: 600 мА; Диапазон рабочих температур: от -60 до +125 ℃; Упаковка: Катушка и лента; Типоразмер: 1608 (0603); Технология монтажа: SMT; Изготовитель: АО "НПО "ЭРКОН"
footprint КИК-1608_Зл (Катушка индуктивности с керамическим сердечником  типоразмер 1005(0402))
pins: 1, 2

## КИК-1608-51 нГн ±2% O
designator L?, comment 51 нГн ±2%  (value not drawn)
Катушка индуктивности с керамическим сердечником и  финишным покрытием контактных площадок оловом; Номиналиная индуктивность: 51 нГн; Добротность, не менее: 35; Резонансная частота, не менее: 1.90 ГГц; Сопротивление обмотки постоянноми току, не более: 0.280 Ом; Допустимый ток обмотки: 600 мА; Диапазон рабочих температур: от -60 до +125 ℃; Упаковка: Катушка и лента; Типоразмер: 1608 (0603); Технология монтажа: SMT; Изготовитель: АО "НПО "ЭРКОН"
footprint КИК-1608_О (Катушка индуктивности с керамическим сердечником  типоразмер 1005(0402))
pins: 1, 2

## КИК-1608-51 нГн ±2% Зл
designator L?, comment 51 нГн ±2%  (value not drawn)
Катушка индуктивности с керамическим сердечником и золотым покрытием контактных площадок; Номиналиная индуктивность: 51 нГн; Добротность, не менее: 35; Резонансная частота, не менее: 1.90 ГГц; Сопротивление обмотки постоянноми току, не более: 0.280 Ом; Допустимый ток обмотки: 600 мА; Диапазон рабочих температур: от -60 до +125 ℃; Упаковка: Катушка и лента; Типоразмер: 1608 (0603); Технология монтажа: SMT; Изготовитель: АО "НПО "ЭРКОН"
footprint КИК-1608_Зл (Катушка индуктивности с керамическим сердечником  типоразмер 1005(0402))
pins: 1, 2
